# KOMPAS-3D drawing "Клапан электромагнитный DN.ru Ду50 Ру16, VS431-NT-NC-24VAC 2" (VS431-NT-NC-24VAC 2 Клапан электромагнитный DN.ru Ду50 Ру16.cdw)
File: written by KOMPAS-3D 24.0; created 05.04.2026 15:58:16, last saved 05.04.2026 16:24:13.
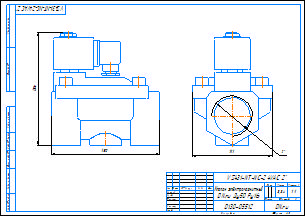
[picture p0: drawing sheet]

Document properties: c3d_UniqueCompID: ef56311e-7521-43dc-8291-0e6108b3d81d; Автор: artio; Класс точности: c; Знак неуказанной шероховатости: Шероховатость не задана; Рассекать на разрезах: Да; c3d_UniqueCompID: ef56311e-7521-43dc-8291-0e6108b3d81d; Автор: artio; Класс точности: c; Знак неуказанной шероховатости: Шероховатость не задана; Рассекать на разрезах: Да; c3d_UniqueCompID: ef56311e-7521-43dc-8291-0e6108b3d81d; Автор: artio; Класс точности: c; Знак неуказанной шероховатости: Шероховатость не задана; Рассекать на разрезах: Да; c3d_UniqueCompID: ef56311e-7521-43dc-8291-0e6108b3d81d; Автор: artio; Класс точности: c; Знак неуказанной шероховатости: Шероховатость не задана; Рассекать на разрезах: Да; c3d_UniqueCompID: ef56311e-7521-43dc-8291-0e6108b3d81d; Автор: artio; Класс точности: c; Знак неуказанной шероховатости: Шероховатость не задана; Рассекать на разрезах: Да; Автор: artio; Форматы листов документа: A3; Полное имя файла: VS431-NT-NC-24VAC 2 Клапан электромагнитный DN.ru Ду50 Ру16.m3d; Масса: 3.341; Наименование: Клапан электромагнитный DN.ru Ду50 Ру16; Количество листов документа: 1; Примечание: D130-05512

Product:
- Body: Тело 1  | qty 1
    Масса: 6.703651
- Part/product: Клапан электромагнитный DN.ru Ду50 Ру16  | designation VS431-NT-NC-24VAC 2
    Масса: 3.341
    Раздел спецификации: Прочие изделия
    Примечание: D130-05512
    additional columns: ef56311e-7521-43dc-8291-0e6108b3d81d; artio; c; Шероховатость не задана; Да

Views: Вид 1, Спереди
Referenced files in C:\Users\artio\OneDrive\Рабочий стол\Клапан электромагнитный DN.ru\VS431\VS431-ET-NC\: VS431-ET-NC-24VAC 3-4 Клапан электромагнитный DN.ru Ду20 Ру16.m3d, VS431-ET-NC-24VAC 3-4 Клапан электромагнитный DN.ru Ду20 Ру16.cdw
Referenced files in C:\Users\artio\OneDrive\Рабочий стол\Клапан электромагнитный DN.ru\VS431\VS431-NT-NC\: VS431-NT-NC-24VAC 2 Клапан электромагнитный DN.ru Ду50 Ру16.m3d
Referenced files in C:\Users\artio\OneDrive\Рабочий стол\Клапан электромагнитный DN.ru\VS431\VS431-NT-NC\VS431-NT-NC-24VAC\Ду50\: VS431-NT-NC-24VAC 2 Клапан электромагнитный DN.ru Ду50 Ру16.m3d
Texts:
  VS431-NT-NC-24VAC 2
  Клапан электромагнитный
  DN.ru Ду50 Ру16
  VS431-NT-NC-24VAC 2"
  VS431-NT-NC-24VAC 2"-
  Клапан электромагнитный DN.ru Ду50 Ру16
  VS431-NT-NC-24VAC 2 Клапан электромагнитный DN.ru Ду50 Ру16
Dimensions and other numbers on the sheet: 0; 3; 2; 4; 111; 1:1; 1; 3,34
